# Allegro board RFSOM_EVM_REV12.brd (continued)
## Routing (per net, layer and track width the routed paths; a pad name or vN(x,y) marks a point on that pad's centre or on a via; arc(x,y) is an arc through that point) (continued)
DVDDL: length 8.6
  TOP w0.203: 377.1,63.21 U12.38
  TOP w0.305: v1(376.78,63.21) 377.1,63.21
  TOP w0.381: v1(374.49,59.45) 374.83,59.79 FB9.1 375.27,59.11 v1(374.49,58.33)
  ART10 w0.508: v1(376.78,63.21) 376.78,61.86 374.49,59.56 v1(374.49,59.45)
VBUS: length 9.4
  TOP w0.381: D2.2 v1(397.99,4.42) ; 394.61,12.7 v1(395.15,12.17) ; 394.61,12.7 v1(394.08,12.17) ; 394.61,12.7 C15.1 ; D1.2 v1(396.09,11.86) ; J4.A9 v1(398.83,9.62) ; J4.B4 v1(400.53,9.37) ; J4.B9 v1(401.98,6.87) ; U9.1 v1(393.87,-1.46) ; J4.A4 v1(398.83,6.62) ; U9.3 v1(395.77,-1.46)
  BOTTOM w0.508: v1(396.09,11.86) 396.54,12.31 C16.1
VCC_1V8_FT: length 9.5
  TOP w0.254: v1(380.08,-1.47) 380.58,-0.97 U2.49 ; U2.37 379.24,5.61 v1(378.99,5.86) ; v1(388.32,-1.47) 388.08,-1.23 U2.64 ; U2.12 v1(389.66,5.61)
  BOTTOM w0.381: v1(389.66,5.61) 388.54,6.73 C25.1
  BOTTOM w0.508: C28.1 v1(378.99,5.86) ; v1(380.08,-1.47) 379.68,-1.87 C26.1 ; C27.1 v1(388.32,-1.47)
VCC_3V3_FT: length 35
  TOP w0.254: v1(386.33,9.2) 386.58,8.95 U2.20 ; U2.42 v1(378.99,3.11) ; U2.31 v1(381.08,9.2) ; U2.56 v1(384.08,-1.47) ; U2.50 v1(381.08,-1.47)
  TOP w0.381: U4.1 v1(390.86,13.23) C3.1 ; C1.1 v1(382.48,13.23) U3.1 ; C5.1 v1(388.06,13.23) U5.1 ; U5.5 v1(388.72,17.12) ; U8.1 v1(376.89,13.23) C17.1 ; U9.5 v1(393.87,3.24) ; U10.8 v1(377.8,-5.35) ; U3.5 v1(383.13,17.12) ; U4.5 v1(391.52,17.12) ; U6.1 v1(385.27,13.23) C7.1 ; U7.5 v1(380.34,17.12) ; FB1.1 v1(391.82,-1.71) ; U7.1 v1(379.68,13.23) C12.1
  BOTTOM w0.381: C22.1 386.05,8.92 v1(386.33,9.2) 387.02,8.51 C21.1
  BOTTOM w0.508: C20.1 378.93,3.17 v1(378.99,3.11) ; C9.1 380.54,-0.43 381.08,-0.97 v1(381.08,-1.47) ; C24.1 394.41,2.7 v1(393.87,3.24) ; R20.2 v1(384.62,-2.6) ; R20.2 R19.2 384.21,-1.6 v1(384.08,-1.47) 384.07,-1.47 383.57,-0.96 C10.1 ; R20.2 R17.2 ; C19.1 v1(381.08,9.2) ; U10.8 v1(377.8,-5.35)
  vias: v1(392.75,7.76) v1(392.75,6.49)
VCC_5V: length 28.4
  TOP w0.254: v1(385.44,39.06) U15.21
  TOP w0.381: J1.C1 v1(228.1,91.77) ; U19.C1 v1(232.85,119.81) ; J1.B2 v1(229.37,90.5) ; U19.G1 v1(239.2,119.81) ; J1.E1 v1(224.29,91.77) ; J2.F1 v1(321.98,91.77) ; J1.B1 v1(229.37,91.77) ; U19.D2 v1(234.12,121.08) ; J1.E2 v1(224.29,90.5) ; J1.G1 v1(221.75,91.77) ; U19.F1 v1(236.66,119.81) ; U19.J1 v1(241.74,119.81) ; U19.D1 v1(234.12,119.81) ; J2.G2 v1(320.71,90.5) ; J1.G2 v1(221.75,90.5) ; U19.K2 v1(243.01,121.08) ; J1.F1 v1(223.02,91.77) ; U19.A2 v1(230.31,121.08) ; U17.7 v1(392.89,30.78) ; U19.G2 v1(239.2,121.08) ; J1.C2 v1(228.1,90.5) ; J2.G1 v1(320.71,91.77) ; J1.D1 v1(226.83,91.77) ; U19.A3 v1(230.31,122.35) ; U19.A1 v1(230.31,119.81) ; J1.F2 v1(223.02,90.5) ; U19.K1 v1(243.01,119.81) ; J1.D2 v1(226.83,90.5)
  BOTTOM w0.508: RP12.1 236.02,120.45 v1(236.66,119.81)
  vias: v1(221.75,92.77) v1(225.56,91.77) v1(225.56,90.77) v1(225.56,89.77) v1(226.83,92.77) v1(228.1,92.77) v1(229.37,92.77) v1(230.66,106.81) v1(230.66,105.81) v1(231.66,111.81) v1(231.66,110.81) v1(231.66,106.81) v1(231.66,105.81) v1(232.66,118.81) v1(232.66,117.81) v1(232.66,116.81) v1(232.66,115.81) v1(232.66,111.81) v1(232.66,110.81) v1(232.66,106.81) v1(232.66,105.81) v1(233.66,118.81) v1(233.66,117.81) v1(233.66,116.81) v1(233.66,115.81) v1(233.66,114.81) v1(233.66,113.81) v1(233.66,112.81) v1(233.66,111.81) v1(233.66,110.81) v1(233.66,109.81) v1(233.66,108.81) v1(233.66,107.81) v1(233.66,106.81) v1(233.66,105.81) v1(234.66,118.81) v1(234.66,117.81) v1(234.66,116.81) v1(234.66,115.81) v1(234.66,114.81) v1(234.66,113.81) v1(234.66,112.81) v1(234.66,111.81) v1(234.66,110.81) v1(234.66,109.81) v1(234.66,108.81) v1(234.66,107.81) v1(234.66,106.81) v1(234.66,105.81) v1(235.66,118.81) v1(235.66,117.81) v1(235.66,116.81) v1(235.66,115.81) v1(235.66,114.81) v1(235.66,113.81) v1(235.66,112.81) v1(235.66,111.81) v1(235.66,110.81) v1(235.66,109.81) v1(235.66,108.81) v1(235.66,107.81) v1(235.66,106.81) v1(235.66,105.81) v1(236.66,118.81) v1(236.66,117.81) v1(236.66,116.81) v1(236.66,115.81) v1(236.66,114.81) v1(236.66,113.81) v1(236.66,112.81) v1(236.66,111.81) v1(236.66,110.81) v1(236.66,109.81) v1(236.66,108.81) v1(236.66,107.81) v1(236.66,106.81) v1(236.66,105.81) v1(237.66,118.81) v1(237.66,117.81) v1(237.66,116.81) v1(237.66,115.81) v1(237.66,114.81) v1(237.66,113.81) v1(237.66,112.81) v1(237.66,111.81) v1(237.66,110.81) v1(237.66,109.81) v1(237.66,108.81) v1(237.66,107.81) v1(237.66,106.81) v1(237.66,105.81) v1(238.66,118.81) v1(238.66,117.81) v1(238.66,116.81) v1(238.66,115.81) v1(238.66,114.81) v1(238.66,113.81) v1(238.66,112.81) v1(238.66,111.81) v1(238.66,110.81) v1(238.66,109.81) v1(238.66,108.81) v1(238.66,107.81) v1(238.66,106.81) v1(238.66,105.81) v1(239.66,118.81) v1(239.66,117.81) v1(239.66,116.81) v1(239.66,115.81) v1(239.66,114.81) v1(239.66,113.81) v1(239.66,112.81) v1(239.66,111.81) v1(239.66,110.81) v1(239.66,109.81) v1(239.66,108.81) v1(239.66,107.81) v1(239.66,106.81) v1(239.66,105.81) v1(240.66,118.81) v1(240.66,117.81) v1(240.66,116.81) v1(240.66,115.81) v1(240.66,114.81) v1(240.66,113.81) v1(240.66,112.81) v1(240.66,111.81) v1(240.66,110.81) v1(240.66,109.81) v1(240.72,108.83) v1(240.66,107.81) v1(240.66,106.81) v1(240.66,105.81) v1(241.66,118.81) v1(241.66,117.81) v1(241.66,116.81) v1(241.66,115.81) v1(241.66,111.81) v1(241.66,110.81) v1(241.66,106.81) v1(241.66,105.81) v1(242.66,118.81) v1(242.66,117.81) v1(242.66,116.81) v1(242.66,115.81) v1(242.66,111.81) v1(242.66,110.81) v1(242.66,106.81) v1(242.66,105.81) v1(243.66,117.81) v1(243.66,116.81) v1(243.66,115.81) v1(243.66,111.81) v1(243.66,110.81) v1(243.66,106.81) v1(243.66,105.81)
VCC_12V: length 15.2
  TOP w0.381: U19.L4 v1(244.28,124.89) ; 299.61,118.16 299.05,118.16 v1(298.09,117.21) ; U19.H5 v1(240.47,126.16) ; U19.B3 v1(231.58,122.35) ; U19.L5 v1(244.28,126.16) ; U19.E3 v1(235.39,122.35) ; U19.B5 v1(231.58,126.16) ; U19.E5 v1(235.39,126.16) ; U19.B4 v1(231.58,124.89) ; U19.E4 v1(235.39,124.89) ; U19.H3 v1(240.47,122.35) ; U19.L3 v1(244.28,122.35) ; U19.H4 v1(240.47,124.89)
  BOTTOM w0.508: RP3.1 231.91,126.49 v1(231.58,126.16) ; v1(240.47,126.16) 240.5,126.16 RP5.1 ; RP6.1 v1(242.13,131.8) ; v1(235.39,126.16) 235.72,126.49 RP4.1
  vias: v1(225.23,131.24) v1(225.23,129.97) v1(225.23,128.7) v1(225.23,127.43) v1(225.23,126.16) v1(225.23,124.89) v1(225.23,123.62) v1(225.23,122.35) v1(225.23,121.08) v1(225.23,119.81) v1(225.23,118.54) v1(226.5,131.24) v1(226.5,129.97) v1(226.5,128.7) v1(226.5,127.43) v1(226.5,126.16) v1(226.5,124.89) v1(226.5,123.62) v1(226.5,122.35) v1(226.5,121.08) v1(226.5,119.81) v1(226.5,118.54) v1(227.77,131.24) v1(227.77,129.97) v1(227.77,128.7) v1(227.77,127.43) v1(227.77,126.16) v1(227.77,124.89) v1(227.77,123.62) v1(227.77,122.35) v1(227.77,121.08) v1(227.77,119.81) v1(227.77,118.54) v1(245.17,126.85) v1(245.17,125.58) v1(245.17,124.31) v1(245.17,123.04) v1(245.17,121.77) v1(245.17,120.5) v1(246.44,126.85) v1(246.44,125.58) v1(246.44,124.31) v1(246.44,123.04) v1(246.44,121.77) v1(246.44,120.5) v1(290.47,117.21) v1(290.47,115.94) v1(290.47,114.67) v1(291.74,117.21) v1(291.74,115.94) v1(291.74,114.67) v1(293.01,117.21) v1(293.01,115.94) v1(293.01,114.67) v1(294.28,117.21) v1(294.28,115.94) v1(294.28,114.67) v1(295.55,117.21) v1(295.55,115.94) v1(295.55,114.67) v1(296.82,117.21) v1(296.82,115.94) v1(296.82,114.67) v1(298.09,115.94) v1(298.09,114.67) v1(299.36,117.21) v1(299.36,115.94) v1(299.36,114.67) v1(300.63,117.21) v1(300.63,115.94) v1(300.63,114.67) v1(301.9,117.21) v1(301.9,115.94) v1(301.9,114.67) v1(303.17,117.21) v1(303.17,115.94) v1(303.17,114.67) v1(304.44,117.21) v1(304.44,115.94) v1(304.44,114.67) v1(359.54,39.12) v1(359.54,37.85) v1(359.54,36.58) v1(359.54,34.04) v1(359.54,32.77) v1(359.54,31.5) v1(359.54,30.23) v1(359.54,28.96) v1(359.54,27.69) v1(359.54,26.42) v1(359.54,25.15) v1(359.54,23.88) v1(359.54,22.61) v1(359.54,21.34) v1(359.54,20.07) v1(359.54,18.8) v1(359.54,17.53) v1(359.54,14.99) v1(359.54,13.72) v1(359.54,12.45) v1(359.54,11.18) v1(359.54,9.91) v1(359.54,8.64) v1(359.54,7.37) v1(360.81,39.12) v1(360.81,37.85) v1(360.81,36.58) v1(360.81,34.04) v1(360.81,32.77) v1(360.81,31.5) v1(360.81,30.23) v1(360.81,28.96) v1(360.81,27.69) v1(360.81,26.42) v1(360.81,25.15) v1(360.81,23.88) v1(360.81,22.61) v1(360.81,21.34) v1(360.81,20.07) v1(360.81,18.8) v1(360.81,17.53) v1(360.81,14.99) v1(360.81,13.72) v1(360.81,12.45) v1(360.81,11.18) v1(360.81,9.91) v1(360.81,8.64) v1(360.81,7.37)
VCCO_89: length 2.7
  TOP w0.381: J2.B2 v1(328.33,90.5) ; J2.C2 v1(327.06,90.5) ; J2.C1 v1(327.06,91.77)
  vias: v1(322.63,107.16) v1(322.63,105.89) v1(322.63,104.62) v1(323.9,107.16) v1(323.9,105.89) v1(323.9,104.62) v1(325.17,107.16) v1(325.17,105.89) v1(325.17,104.62) v1(326.44,107.16) v1(326.44,105.89) v1(326.44,104.62)
VCCO_501: length 2.7
  TOP w0.381: J2.F2 v1(321.98,90.5) ; J2.E1 v1(323.25,91.77) ; J2.E2 v1(323.25,90.5)
  vias: v1(313.28,107.16) v1(313.28,105.89) v1(313.28,104.62) v1(314.55,107.16) v1(314.55,105.89) v1(314.55,104.62) v1(315.82,107.16) v1(315.82,105.89) v1(315.82,104.62) v1(317.09,107.16) v1(317.09,105.89) v1(317.09,104.62)
VCCO_502: length 2.7
  TOP w0.381: J2.D1 v1(325.79,91.77) ; J2.B1 v1(328.33,91.77) ; J2.D2 v1(325.79,90.5)
  vias: v1(317.96,107.16) v1(317.96,105.89) v1(317.96,104.62) v1(319.23,107.16) v1(319.23,105.89) v1(319.23,104.62) v1(320.5,107.16) v1(320.5,105.89) v1(320.5,104.62) v1(321.77,107.16) v1(321.77,105.89) v1(321.77,104.62)
VDD33: length 1.4
  TOP w0.203: v1(379.22,60.48) 379.22,60.86 379.44,61.08 U12.3
VDDH: length 9.3
  TOP w0.203: U12.8 381.44,59.27 v1(382.37,58.33) ; U12.27 v1(379.84,67.46)
  TOP w0.381: RL10.2 374.57,62.24 v1(374.34,62.01) ; RL15.2 v1(382.2,71.04) ; RL14.2 v1(381.2,71.04) ; RL21.2 v1(376.2,71.04) ; RL11.2 v1(384.2,71.04)
  BOTTOM w0.254: CL18.2 v1(382.37,58.33)
  BOTTOM w0.508: CL17.2 379.69,67.32 v1(379.84,67.46)
BANK128_MGT_CLK1_N: length 33.6
  TOP w0.114: v1(337.76,24.04) 337.59,24.2 arc(337.48,24.37) 337.44,24.57 337.44,24.69 arc(337.49,24.8) 337.6,24.85 340.79,24.85 arc(341.05,24.8) 341.27,24.65 341.29,24.63 arc(341.51,24.48) 341.77,24.43 XS1.5
  TOP w0.173: J2.E40 v1(324.52,42.24)
  ART05 w0.102: v1(337.76,24.04) 337.49,24.3 arc(337.46,24.36) 337.44,24.42 337.44,25.63 arc(337.29,26.4) 336.86,27.04 335.79,28.12 arc(335.39,28.71) 335.25,29.41 335.25,35.5 arc(333.42,39.92) 329,41.75 324.62,41.75 arc(324.55,41.78) 324.52,41.85 v1(324.52,42.24)
BANK128_MGT_CLK1_P: length 33.5
  TOP w0.114: XS1.4 341.77,25.53 arc(341.51,25.48) 341.29,25.34 341.27,25.32 arc(341.05,25.17) 340.79,25.12 337.6,25.12 arc(337.3,24.99) 337.17,24.69 337.17,24.59 arc(337.13,24.38) 337.02,24.21 v1(336.84,24.04)
  TOP w0.173: J2.D40 v1(324.52,40.97)
  ART05 w0.102: v1(324.52,40.97) 324.52,41.36 arc(324.55,41.43) 324.62,41.46 329,41.46 arc(333.22,39.72) 334.96,35.5 334.96,29.41 arc(335.12,28.6) 335.58,27.91 336.66,26.84 arc(337.03,26.29) 337.16,25.63 337.16,24.39 arc(337.15,24.35) 337.13,24.32 v1(336.84,24.04)
BANK128_MGT_RX0_N: length 75.7
  TOP w0.114: J12.18 359.12,91.53 arc(359.28,91.5) 359.42,91.4 359.44,91.39 arc(359.58,91.29) 359.74,91.26 359.79,91.26 arc(359.98,91.3) 360.14,91.41 v1(360.32,91.59)
  TOP w0.173: J2.C39 v1(327.06,42.24)
  ART10 w0.102: v1(327.06,42.24) 327.49,42.67 arc(327.59,42.74) 327.71,42.76 328.66,42.76 330.16,42.49 332.73,42.95 336.09,42.35 338.11,42.71 339.83,43.91 341.79,44.26 344.15,45.91 346.07,48.65 347.85,49.89 348.93,51.44 350.28,52.39 351.35,53.91 351.64,55.56 353.48,58.18 356.39,60.22 359.09,64.08 359.92,68.78 359.41,71.7 360.04,75.28 361.47,77.33 361.84,79.42 361.65,80.47 361.79,81.25 362.66,82.49 363,84.44 363,90.15 arc(362.68,90.93) 361.91,91.25 360.75,91.25 arc(360.67,91.26) 360.59,91.31 v1(360.32,91.59)
BANK128_MGT_RX0_P: length 75.7
  TOP w0.114: J12.17 359.12,90.73 arc(359.28,90.76) 359.42,90.85 359.44,90.87 arc(359.58,90.96) 359.74,90.99 359.79,90.99 arc(359.98,90.96) 360.14,90.85 v1(360.32,90.67)
  TOP w0.173: J2.B39 v1(327.06,43.51)
  ART10 w0.102: v1(360.32,90.67) 360.59,90.94 arc(360.67,90.99) 360.75,91.01 361.91,91.01 arc(362.52,90.76) 362.77,90.15 362.77,89.85 362.55,89.63 362.55,89.44 362.77,89.23 362.77,89.04 362.55,88.82 362.55,88.63 362.77,88.41 362.77,88.22 362.55,88.01 362.55,87.82 362.77,87.6 362.77,87.41 362.55,87.19 362.55,87 362.77,86.79 362.77,84.46 362.44,82.58 361.57,81.34 361.41,80.47 361.6,79.42 361.25,77.42 359.81,75.38 359.17,71.7 359.68,68.78 358.87,64.17 356.22,60.39 353.31,58.35 351.42,55.65 351.13,54 350.11,52.56 348.76,51.61 347.68,50.06 345.9,48.82 343.98,46.08 341.7,44.48 339.74,44.14 338.02,42.93 336.09,42.59 332.73,43.19 330.16,42.73 328.68,43 327.71,43 arc(327.59,43.02) 327.49,43.08 v1(327.06,43.51)
BANK128_MGT_RX1_N: length 69.3
  TOP w0.114: J12.21 355.35,91.13 arc(355.22,91.1) 355.11,91.03 355.04,90.96 arc(354.93,90.89) 354.81,90.86 354.79,90.86 arc(354.66,90.89) 354.56,90.96 v1(354.33,91.18)
  TOP w0.173: J2.G37 v1(321.98,46.05)
  ART10 w0.102: v1(321.98,46.05) 322.41,45.62 arc(322.51,45.56) 322.63,45.54 326.03,45.54 arc(326.18,45.59) 326.24,45.74 326.24,46.38 arc(326.36,46.67) 326.64,46.79 328.02,46.79 328.65,46.9 328.75,46.9 328.75,46.9 329.68,46.9 330.3,46.79 331.83,47.06 332.77,47.72 334.98,48.11 336.12,48.9 337.73,49.19 338.97,50.06 339.82,51.26 341.21,52.24 342.9,54.66 343.13,55.93 344.17,57.41 345.16,63.02 344.91,64.44 345.27,66.48 344.8,69.14 345.23,71.57 344.77,74.14 345.04,75.64 344.85,76.74 344.85,76.75 344.84,76.76 345.9,82.73 350.78,89.7 352.07,90.61 353.42,90.85 353.9,90.85 arc(353.98,90.86) 354.06,90.91 v1(354.33,91.18)
BANK128_MGT_RX1_P: length 69.3
  TOP w0.114: J12.22 355.35,90.33 arc(355.22,90.35) 355.11,90.43 355.04,90.5 arc(354.94,90.57) 354.81,90.59 354.79,90.59 arc(354.66,90.57) 354.56,90.5 v1(354.33,90.27)
  TOP w0.173: J2.F37 v1(321.98,44.78)
  ART10 w0.102: v1(321.98,44.78) 322.41,45.21 arc(322.51,45.28) 322.63,45.3 326.03,45.3 arc(326.35,45.43) 326.47,45.74 326.47,46.38 arc(326.52,46.5) 326.64,46.55 328.04,46.55 328.65,46.66 328.75,46.66 328.75,46.66 329.66,46.66 330.3,46.55 331.92,46.83 332.87,47.49 335.08,47.88 336.21,48.68 337.82,48.96 339.14,49.89 339.99,51.09 341.38,52.07 343.13,54.57 343.35,55.84 344.39,57.32 345.4,63.02 345.15,64.44 345.51,66.48 345.04,69.14 345.47,71.57 345.01,74.14 345.28,75.64 345.08,76.76 346.12,82.64 350.95,89.53 352.16,90.38 353.44,90.61 353.9,90.61 arc(353.98,90.59) 354.06,90.54 v1(354.33,90.27)
BANK128_MGT_RX2_N: length 71.8
  TOP w0.114: J12.15 359.12,89.13 arc(359.28,89.1) 359.42,89 359.44,88.99 arc(359.58,88.89) 359.74,88.86 359.79,88.86 arc(359.98,88.9) 360.14,89.01 v1(360.32,89.19)
  TOP w0.173: v1(324.52,44.78) J2.E38
  ART10 w0.102: v1(324.52,44.78) 324.95,44.35 arc(325.05,44.29) 325.17,44.27 328.25,44.27 329.46,44.48 330.34,44.32 331.5,44.53 332.87,44.29 334.25,44.53 334.95,45.02 336.36,45.27 337.73,46.23 339.1,46.47 340.13,47.19 341.79,47.49 343.21,48.48 345.12,51.2 345.32,52.34 346.22,53.62 346.53,55.37 348.54,58.25 349.81,65.44 349.14,69.23 349.65,72.1 349.21,74.62 350.47,81.8 351.06,82.63 352.78,83.84 354.49,84.14 355.19,84.63 355.89,85.63 356.28,87.81 356.53,88.17 357.28,88.7 358.11,88.85 359.74,88.85 arc(359.96,88.89) 360.15,89.02 v1(360.32,89.19)
BANK128_MGT_RX2_P: length 71.8
  TOP w0.114: v1(360.32,88.27) 360.14,88.45 arc(359.98,88.56) 359.79,88.59 359.74,88.59 arc(359.58,88.56) 359.44,88.47 359.42,88.45 arc(359.28,88.36) 359.12,88.33 J12.14
  TOP w0.173: v1(324.52,43.51) J2.D38
  ART10 w0.102: v1(360.32,88.27) 360.15,88.44 arc(359.96,88.56) 359.74,88.61 359.17,88.61 arc(359.17,88.61) 359.16,88.61 358.14,88.61 357.38,88.48 356.7,88 356.5,87.72 356.12,85.54 355.36,84.46 354.59,83.92 352.87,83.62 351.22,82.46 350.7,81.71 349.45,74.62 349.89,72.1 349.38,69.23 350.05,65.44 348.77,58.16 346.75,55.28 346.44,53.53 345.54,52.25 345.34,51.11 343.38,48.31 341.89,47.26 340.22,46.97 339.19,46.25 337.83,46.01 336.45,45.04 335.04,44.8 334.34,44.31 332.87,44.05 331.5,44.29 330.34,44.08 329.46,44.24 328.27,44.03 325.17,44.03 arc(325.05,44.01) 324.95,43.94 v1(324.52,43.51)
BANK128_MGT_RX3_N: length 63.2
  TOP w0.114: J12.24 355.35,88.73 arc(355.22,88.7) 355.11,88.63 355.04,88.56 arc(354.93,88.49) 354.81,88.46 354.79,88.46 arc(354.66,88.49) 354.56,88.56 v1(354.33,88.78)
  TOP w0.173: J2.C37 v1(327.06,46.05)
  ART10 w0.102: v1(354.33,88.78) 354.06,88.52 arc(353.98,88.46) 353.89,88.45 353.43,88.45 352.59,88.3 351.85,87.78 351.46,87.23 351.29,86.23 348.37,82.06 347.7,78.28 347.95,76.86 347.23,72.78 347.45,71.55 347.06,69.35 347.24,68.35 347.56,66.5 347.23,64.63 347.6,62.5 347.27,60.59 346.35,59.28 345.98,57.15 345.03,55.8 344.77,54.28 343.82,52.93 343.51,51.16 342.61,49.88 341.01,48.76 339.89,48.56 338.68,47.71 337.43,47.49 336.27,46.67 334.75,46.41 333.67,45.65 332.21,45.39 331.07,45.59 329.92,45.39 329.09,45.54 327.71,45.54 arc(327.59,45.56) 327.49,45.62 v1(327.06,46.05)
BANK128_MGT_RX3_P: length 63.2
  TOP w0.114: J12.25 355.36,87.93 355.35,87.93 arc(355.22,87.95) 355.11,88.03 355.04,88.1 arc(354.94,88.17) 354.81,88.19 354.79,88.19 arc(354.66,88.17) 354.56,88.1 v1(354.33,87.87)
  TOP w0.173: J2.B37 v1(327.06,44.78)
  ART10 w0.102: v1(327.06,44.78) 327.49,45.21 arc(327.59,45.28) 327.71,45.3 329.07,45.3 329.92,45.15 331.07,45.35 332.21,45.15 333.76,45.43 334.84,46.18 336.36,46.45 337.52,47.26 338.77,47.48 339.99,48.34 341.1,48.53 342.78,49.71 343.73,51.06 344.04,52.84 344.99,54.19 345.26,55.71 346.2,57.06 346.58,59.19 347.49,60.5 347.84,62.5 347.47,64.63 347.8,66.5 347.47,68.39 347.3,69.35 347.69,71.55 347.47,72.78 348.19,76.86 347.94,78.28 348.59,81.97 351.51,86.14 351.69,87.14 352.02,87.61 352.68,88.07 353.45,88.21 353.89,88.21 arc(353.98,88.19) 354.06,88.14 v1(354.33,87.87)
BANK128_MGT_TX0_N: length 65.8
  TOP w0.114: J12.37 355.35,78.33 arc(355.22,78.35) 355.11,78.43 355.04,78.5 arc(354.94,78.57) 354.81,78.59 354.79,78.59 arc(354.66,78.57) 354.56,78.5 354.33,78.27
  TOP w0.173: J2.G41 321.98,39.7
  ART03 w0.102: 354.33,78.27 354.04,78.56 arc(353.98,78.6) 353.92,78.61 352.78,78.61 350.05,78.13 350.01,78.12 349.26,77.99 347,76.41 345.75,74.62 344.91,69.82 345.95,63.93 345.44,61.09 345.82,58.96 344.91,53.78 343.51,51.78 342.97,48.71 341.09,46.02 338.72,44.37 334.82,43.68 330.75,44.4 328.71,44.04 325.85,44.04 arc(325.7,44.01) 325.58,43.93 325.49,43.84 325.48,43.83 arc(325.4,43.71) 325.37,43.57 325.37,43.39 arc(325.33,43.18) 325.22,43.01 325.15,42.94 arc(324.94,42.81) 324.7,42.76 324.29,42.76 arc(324.17,42.74) 324.08,42.67 324.02,42.61 arc(323.94,42.5) 323.92,42.36 323.92,40.89 arc(323.88,40.7) 323.77,40.54 323.62,40.39 arc(323.43,40.26) 323.22,40.22 322.79,40.22 arc(322.52,40.17) 322.3,40.02 321.98,39.7
BANK128_MGT_TX0_P: length 65.8
  TOP w0.114: J12.36 355.35,79.13 arc(355.22,79.1) 355.11,79.03 355.04,78.96 arc(354.93,78.89) 354.81,78.86 354.79,78.86 arc(354.66,78.89) 354.56,78.96 354.33,79.18
  TOP w0.173: J2.F41 321.98,40.97
  ART03 w0.102: 354.33,79.18 354.04,78.9 arc(353.98,78.86) 353.92,78.85 352.76,78.85 350.01,78.36 349.17,78.21 346.83,76.58 345.53,74.71 344.67,69.82 345.71,63.93 345.2,61.09 345.58,58.96 344.68,53.87 343.28,51.87 342.74,48.8 340.92,46.19 338.63,44.59 334.82,43.92 330.75,44.64 328.68,44.28 325.85,44.28 arc(325.61,44.23) 325.41,44.09 325.31,44 arc(325.18,43.8) 325.14,43.57 325.14,43.39 arc(325.11,43.27) 325.05,43.18 324.98,43.11 arc(324.85,43.02) 324.7,42.99 324.29,42.99 arc(324.08,42.95) 323.91,42.84 323.85,42.78 arc(323.72,42.59) 323.68,42.36 323.68,40.89 arc(323.66,40.79) 323.6,40.7 323.45,40.55 arc(323.34,40.48) 323.22,40.46 322.73,40.46 arc(322.52,40.5) 322.34,40.62 321.98,40.97
BANK128_MGT_TX1_N: length 73.9
  TOP w0.114: 360.32,78.67 360.15,78.84 arc(359.98,78.95) 359.78,78.99 359.69,78.99 arc(359.53,78.96) 359.39,78.87 359.37,78.85 arc(359.23,78.76) 359.07,78.73 J12.2
  TOP w0.173: J2.E42 324.52,39.7
  ART03 w0.102: 324.52,39.7 324.84,39.39 arc(325.06,39.24) 325.33,39.19 325.77,39.19 arc(325.92,39.22) 326.05,39.3 326.13,39.38 arc(326.18,39.46) 326.2,39.56 326.2,41.12 arc(326.24,41.31) 326.35,41.47 326.41,41.54 arc(326.61,41.67) 326.84,41.71 329.16,41.71 331.56,41.29 332.83,41.51 334.21,41.27 338.96,42.11 343.5,45.29 346.07,48.96 346.64,52.18 347.76,53.77 348.26,56.62 347.54,60.68 348.3,64.97 347.39,70.13 347.86,72.83 349.17,74.7 349.73,75.09 350.06,75.33 352.15,75.7 353.6,75.45 355.62,75.81 355.63,75.8 357.17,75.8 357.46,76.09 357.78,76.09 358.07,75.8 358.39,75.8 358.68,76.09 359,76.09 359.29,75.8 359.61,75.8 359.9,76.09 360.22,76.09 360.51,75.8 360.82,75.8 arc(361.32,76.01) 361.53,76.52 361.53,78.43 arc(361.49,78.67) 361.36,78.86 arc(361.19,78.97) 361,79.01 360.73,79.01 arc(360.66,79) 360.61,78.96 360.32,78.67
BANK128_MGT_TX1_P: length 73.9
  TOP w0.114: 360.32,79.59 360.14,79.41 arc(359.98,79.3) 359.79,79.26 359.74,79.26 arc(359.58,79.29) 359.44,79.39 359.42,79.4 arc(359.28,79.5) 359.12,79.53 J12.3
  TOP w0.173: J2.D42 324.52,38.43
  ART03 w0.102: 360.32,79.59 360.61,79.3 arc(360.66,79.26) 360.73,79.25 361,79.25 arc(361.28,79.19) 361.53,79.03 arc(361.71,78.76) 361.77,78.43 361.77,76.52 arc(361.49,75.85) 360.82,75.57 355.63,75.57 353.6,75.21 352.15,75.46 350.16,75.11 349.87,74.9 349.34,74.53 348.09,72.73 347.63,70.13 348.54,64.97 347.78,60.68 348.5,56.62 347.98,53.68 346.86,52.08 346.29,48.87 343.67,45.12 341.37,43.5 339.05,41.88 334.21,41.03 332.83,41.27 331.56,41.05 329.14,41.48 326.84,41.48 arc(326.7,41.45) 326.58,41.37 326.51,41.3 arc(326.46,41.22) 326.44,41.12 326.44,39.56 arc(326.4,39.37) 326.29,39.21 326.21,39.13 arc(326.01,39) 325.77,38.95 325.33,38.95 arc(325.06,38.9) 324.84,38.75 324.83,38.74 324.52,38.43
BANK128_MGT_TX2_N: length 66.4
  TOP w0.114: 354.33,80.67 354.56,80.9 arc(354.66,80.97) 354.79,80.99 354.81,80.99 arc(354.94,80.97) 355.04,80.9 355.09,80.85 arc(355.23,80.76) 355.39,80.73 J12.34
  TOP w0.173: J2.G39 321.98,42.24
  ART03 w0.102: 354.33,80.67 354.04,80.96 arc(353.98,81) 353.92,81.01 352.87,81.01 351.46,80.76 350.65,80.9 348.88,80.59 345.76,78.41 343.13,74.65 342.46,70.88 343.76,63.53 343.34,61.14 343.74,58.85 343.05,54.9 340.86,51.78 340.49,49.67 339.23,47.88 337.65,46.77 333.93,46.11 330.94,46.64 326.89,46.64 arc(326.58,46.51) 326.45,46.2 326.45,45.96 arc(326.25,45.48) 325.77,45.28 323.12,45.28 arc(322.92,45.2) 322.83,45 322.83,43.14 arc(322.72,42.87) 322.46,42.76 322.08,42.76 arc(322.01,42.73) 321.98,42.66 321.98,42.24
BANK128_MGT_TX2_P: length 66.4
  TOP w0.114: 354.33,81.58 354.56,81.36 arc(354.66,81.29) 354.79,81.26 354.81,81.26 arc(354.93,81.29) 355.04,81.36 355.09,81.4 arc(355.23,81.5) 355.39,81.53 J12.33
  TOP w0.173: J2.F39 321.98,43.51
  ART03 w0.102: 321.98,43.51 321.98,43.1 arc(322.01,43.03) 322.08,43 322.46,43 arc(322.56,43.04) 322.6,43.14 322.6,45 arc(322.75,45.36) 323.12,45.52 325.77,45.52 arc(326.08,45.65) 326.21,45.96 326.21,46.2 arc(326.41,46.68) 326.89,46.88 330.96,46.88 333.93,46.35 337.55,46.99 339.06,48.05 340.26,49.76 340.63,51.87 342.82,54.99 343.5,58.85 343.1,61.14 343.52,63.53 342.22,70.88 342.91,74.74 345.59,78.58 348.78,80.82 350.65,81.14 351.46,81 352.85,81.25 353.92,81.25 arc(353.98,81.26) 354.04,81.3 354.33,81.58
BANK128_MGT_TX3_N: length 75.8
  TOP w0.114: J12.5 359.07,81.13 arc(359.23,81.16) 359.37,81.25 359.39,81.27 arc(359.53,81.36) 359.69,81.39 359.78,81.39 arc(359.98,81.35) 360.15,81.24 360.32,81.07
  TOP w0.173: J2.C41 327.06,40.97
  ART03 w0.102: 327.06,40.97 327.33,40.71 arc(327.61,40.52) 327.94,40.46 328.68,40.46 329.79,40.26 330.67,39.64 332.46,39.33 334.2,39.64 336.64,39.21 339.01,39.62 341.41,41.3 344.31,41.81 345.92,42.94 347.09,44.61 347.47,46.76 348.68,48.5 349.15,51.16 350.49,53.06 351.01,56.04 350.21,60.59 350.75,63.65 351.41,64.6 352.05,65.04 353.27,65.26 354.82,64.99 356.58,65.3 357.67,66.85 358.53,67.45 359.75,68.28 360.16,68.86 362.36,70.4 363.15,71.53 363.97,72.35 arc(364.21,72.71) 364.3,73.13 364.3,75.68 364,75.97 364,76.29 364.3,76.58 364.3,76.9 364,77.19 364,77.51 364.3,77.8 364.3,78.12 364,78.41 364,78.73 364.3,79.02 364.3,80.66 arc(364.08,81.19) 363.55,81.41 360.73,81.41 arc(360.66,81.4) 360.61,81.36 360.32,81.07
BANK128_MGT_TX3_P: length 75.8
  TOP w0.114: 360.32,81.99 360.14,81.81 arc(359.98,81.7) 359.79,81.66 359.74,81.66 arc(359.58,81.69) 359.44,81.79 359.42,81.8 arc(359.28,81.9) 359.12,81.93 J12.6
  TOP w0.173: J2.B41 327.06,39.7
  ART03 w0.102: 360.32,81.99 360.61,81.7 arc(360.66,81.66) 360.73,81.65 363.55,81.65 arc(364.24,81.36) 364.53,80.66 364.53,73.13 arc(364.43,72.62) 364.14,72.19 363.34,71.38 362.53,70.23 360.33,68.69 359.92,68.11 358.57,67.17 358.53,67.16 357.84,66.68 356.72,65.08 354.82,64.75 353.27,65.02 352.14,64.82 351.58,64.43 350.97,63.56 350.45,60.59 351.25,56.04 350.71,52.97 349.38,51.07 348.91,48.41 347.69,46.67 347.31,44.51 346.09,42.77 344.4,41.59 341.5,41.08 339.11,39.4 336.64,38.97 334.2,39.4 332.46,39.09 330.57,39.42 329.69,40.04 328.66,40.22 327.94,40.22 arc(327.61,40.15) 327.33,39.97 327.06,39.7
BANK129_MGT_RX0_N: length 109.6
  TOP w0.114: v1(365.52,132.13) 365.75,131.9 arc(365.85,131.83) 365.98,131.81 366,131.81 arc(366.12,131.83) 366.23,131.9 366.28,131.95 arc(366.41,132.04) 366.58,132.07 J40.12
  TOP w0.173: J2.C31 v1(327.06,53.67)
  ART10 w0.102: v1(365.52,132.13) 365.52,131.89 arc(365.49,131.82) 365.42,131.79 364.08,131.79 361.93,132.17 360.26,131.88 358.81,130.86 354.83,130.16 350.45,127.09 348.82,124.76 344.52,121.75 341.95,118.08 341.13,113.44 342.04,108.31 340.68,100.6 341.5,95.91 340.73,91.55 341.7,86.1 341.1,82.73 341.02,82.25 341.64,78.71 341.25,76.5 341.48,75.23 341.26,73.99 341.73,71.3 341.36,69.2 341.9,66.13 341.6,64.44 341.99,62.26 341.57,59.87 340.59,58.47 340.47,57.79 337.92,54.15 336.85,53.4 334.62,53.01 333.45,53.22 330.88,52.76 328.65,53.16 327.71,53.16 arc(327.59,53.18) 327.49,53.24 v1(327.06,53.67)
BANK129_MGT_RX0_P: length 109.6
  TOP w0.114: v1(365.52,131.22) 365.75,131.45 arc(365.85,131.52) 365.98,131.54 366,131.54 arc(366.13,131.52) 366.23,131.45 366.28,131.4 arc(366.42,131.31) 366.58,131.27 J40.13
  TOP w0.173: J2.B31 v1(327.06,52.4)
  ART10 w0.102: v1(365.52,131.22) 365.52,131.45 arc(365.49,131.53) 365.42,131.56 364.06,131.56 361.93,131.93 360.35,131.65 358.9,130.64 354.93,129.94 350.62,126.92 348.99,124.6 344.69,121.58 342.17,117.99 341.37,113.44 342.28,108.31 340.92,100.6 341.74,95.91 340.97,91.55 341.94,86.1 341.34,82.73 341.26,82.25 341.88,78.71 341.49,76.5 341.72,75.23 341.5,73.99 341.97,71.3 341.6,69.2 342.14,66.13 341.84,64.44 342.23,62.26 341.79,59.78 340.81,58.38 340.69,57.7 338.09,53.98 336.94,53.18 334.62,52.77 333.45,52.98 330.88,52.52 328.63,52.92 327.71,52.92 arc(327.59,52.9) 327.49,52.83 v1(327.06,52.4)
BANK129_MGT_TX0_N: length 111.7
  TOP w0.114: 365.52,126.42 365.75,126.65 arc(365.85,126.72) 365.98,126.74 366,126.74 arc(366.13,126.72) 366.23,126.65 366.28,126.6 arc(366.42,126.51) 366.58,126.47 J40.19
  TOP w0.173: J2.E34 324.52,48.59
  ART03 w0.102: 365.52,126.42 365.52,126.65 arc(365.49,126.73) 365.42,126.76 364.69,126.76 364.15,126.66 361.22,124.61 359.65,124.34 357.13,123.89 354.59,124.34 351.47,123.79 349.16,124.2 346.66,123.75 343.73,121.7 339.69,120.99 336.39,118.68 334.79,116.39 333.9,111.35 334.16,109.86 333.17,104.23 333.9,100.07 332.25,90.69 332.81,87.5 332.1,83.45 332.82,79.39 331.76,73.38 332.29,70.35 331.87,67.93 332.24,65.82 331.26,60.27 332.18,55.07 331.57,51.62 330.4,49.94 329.57,49.37 328.1,49.11 324.62,49.11 arc(324.55,49.08) 324.52,49.01 324.52,48.59
BANK129_MGT_TX0_P: length 111.7
  TOP w0.114: 365.52,127.33 365.75,127.1 arc(365.85,127.03) 365.98,127.01 366,127.01 arc(366.12,127.03) 366.23,127.1 366.28,127.15 arc(366.41,127.24) 366.58,127.27 J40.18
  TOP w0.173: J2.D34 324.52,49.86
  ART03 w0.102: 365.52,127.33 365.52,127.09 arc(365.49,127.02) 365.42,126.99 364.67,126.99 364.05,126.88 361.13,124.84 359.65,124.58 357.13,124.13 354.59,124.58 351.47,124.03 349.16,124.44 346.57,123.98 343.64,121.92 339.6,121.21 336.22,118.85 334.56,116.48 333.66,111.35 333.92,109.86 332.93,104.23 333.66,100.07 332.01,90.69 332.57,87.5 331.87,83.49 331.86,83.45 332.58,79.39 331.53,73.42 331.52,73.38 332.05,70.35 331.63,67.93 332,65.82 331.02,60.27 331.94,55.07 331.34,51.71 330.23,50.11 329.48,49.59 329.48,49.59 328.08,49.35 324.62,49.35 arc(324.55,49.38) 324.52,49.45 324.52,49.86
BANK501_PS_MIO30: length 151.8
  TOP w0.173: J2.D8 v1(325.79,82.88)
  ART10 w0.135: J10.2 235.24,136.45 238.81,136.45 254.18,121.08 258.91,121.08 272.64,107.36 272.64,85.2 284.53,73.3 328.57,73.3 329.16,73.89 329.16,80.16 326.44,82.88 v1(325.79,82.88)
BANK501_PS_MIO31: length 136.5
  TOP w0.173: J2.C15 v1(327.06,73.99)
  ART10 w0.135: J10.3 236,137.69 238.81,137.69 254.16,122.34 259.32,122.34 273.8,107.87 273.8,85.57 284.85,74.52 326.54,74.52 v1(327.06,73.99)
BANK501_PS_MIO32: length 139.8
  TOP w0.173: J2.D10 v1(325.79,80.34)
  ART10 w0.135: v1(325.79,80.34) 326.46,80.34 327.56,79.25 327.56,77.35 327.32,77.11 285.66,77.11 276.67,86.1 276.67,108.8 259.28,126.18 254.29,126.18 240.82,139.65 238.66,139.65 237.37,140.93 237.37,142.2 237.24,142.34 235.4,142.34 J10.4
BANK501_PS_MIO33: length 135.1
  TOP w0.173: J2.B15 v1(328.33,73.99)
  ART10 w0.135: v1(328.33,73.99) 326.41,75.92 284.77,75.92 275.2,85.49 275.2,108.51 258.91,124.8 253.59,124.8 239.55,138.84 237.44,138.84 236.37,139.9 J10.5
BANK501_PS_MIO34: length 123.5
  TOP w0.173: J2.G7 v1(320.71,84.15)
  ART10 w0.135: J10.6 239.83,142.77 257,142.77 257.99,141.78 257.99,137.92 284.47,111.44 284.47,89.09 288.88,84.68 320.18,84.68 v1(320.71,84.15)
BANK501_PS_MIO35: length 127.5
  TOP w0.173: J2.C11 v1(327.06,79.07)
  ART10 w0.135: v1(327.06,79.07) 326.58,78.59 285.89,78.59 278.27,86.21 278.27,109.58 258.47,129.38 257.1,129.38 250.03,136.45 245.24,136.45 J10.7
BANK501_PS_MIO38: length 119.5
  TOP w0.173: J2.G9 v1(320.71,81.61)
  ART10 w0.135: J10.8 243.39,142.33 247.18,142.33 247.4,142.11 247.4,140.11 247.78,139.73 252.98,139.73 282.11,110.6 282.11,87.59 287.1,82.6 319.1,82.6 320.09,81.61 v1(320.71,81.61)
BANK501_PS_MIO39: length 120.2
  TOP w0.173: J2.E10 v1(323.25,80.34)
  ART10 w0.135: v1(323.25,80.34) 322.64,79.73 286.93,79.73 279.65,87 279.65,110.01 251.77,137.9 245.8,137.9 244.37,139.32 J10.9
BANK501_PS_MIO40: length 123.3
  TOP w0.173: J2.B11 v1(328.33,79.07)
  ART10 w0.135: v1(328.33,79.07) 327.86,79.54 327.86,80.42 327.41,80.87 319.2,80.87 318.49,81.58 286.88,81.58 280.93,87.53 280.93,110.54 252.45,139.01 247.5,139.01 246.37,140.14 J10.10
BANK501_PS_MIO41: length 115.4
  TOP w0.173: J2.F9 v1(321.98,81.61)
  ART10 w0.135: J10.11 249.22,142.16 254.86,142.16 255.52,141.5 255.52,138.95 283.06,111.42 283.06,88.41 287.89,83.58 320.81,83.58 321.36,83.03 321.36,82.23 v1(321.98,81.61)
BANK505_MGT_CLK0_N: length 38.4
  TOP w0.114: U13.9 339.05,32.86 338.85,32.66 337.69,32.66 337.42,32.94 337.42,33.36 337.54,33.48 v1(337.75,33.48)
  TOP w0.173: J2.G33 v1(321.98,51.13)
  BOTTOM w0.114: v1(321.98,51.13) 321.98,50.74 322.1,50.63 326.15,50.63 326.48,50.3 326.48,49.56 326.68,49.35 336.07,49.35 339.35,46.07 339.35,39.6 337.42,37.68 337.42,33.59 337.54,33.48 v1(337.75,33.48)
BANK505_MGT_CLK0_P: length 38.4
  TOP w0.114: v1(336.83,33.48) 337.04,33.48 337.16,33.36 337.16,32.82 337.58,32.4 338.85,32.4 339.05,32.21 U13.10
  TOP w0.173: J2.F33 v1(321.98,49.86)
  BOTTOM w0.114: v1(336.83,33.48) 337.04,33.48 337.16,33.59 337.16,37.79 339.08,39.72 339.08,45.96 335.96,49.09 326.57,49.09 326.21,49.44 326.21,50.19 326.04,50.36 322.1,50.36 321.98,50.25 v1(321.98,49.86)
BANK505_MGT_CLK2_N: length 23.4
  TOP w0.114: v1(336.85,40.54) 337.06,40.54 337.18,40.42 337.18,39.79 337.73,39.23 339.18,39.23 339.6,38.82 Y7.5
  TOP w0.173: J2.E36 v1(324.52,46.05)
  BOTTOM w0.114: v1(324.52,46.05) 325.02,46.55 335.44,46.55 337.18,44.82 337.18,40.65 337.06,40.54 v1(336.85,40.54)
BANK505_MGT_CLK2_P: length 23.4
  TOP w0.114: Y7.4 339.6,39.92 339.18,39.5 337.84,39.5 337.45,39.9 337.45,40.42 337.56,40.54 v1(337.77,40.54)
  TOP w0.173: J2.D36 v1(324.52,47.32)
  BOTTOM w0.114: v1(337.77,40.54) 337.56,40.54 337.45,40.65 337.45,44.93 335.55,46.82 325.02,46.82 v1(324.52,47.32)
BANK505_MGT_RX0_N: length 55.6
  TOP w0.114: C72.2 340.07,-1.7 arc(340.24,-1.81) 340.44,-1.85 340.48,-1.85 arc(340.69,-1.81) 340.86,-1.7 341.04,-1.52
  TOP w0.173: J2.E48 324.52,30.81
  ART03 w0.102: 324.52,30.81 324.52,31.1 arc(324.59,31.26) 324.75,31.33 324.86,31.33 arc(324.99,31.35) 325.1,31.43 325.18,31.52 arc(325.31,31.7) 325.35,31.92 325.35,33.54 arc(325.37,33.66) 325.44,33.75 325.46,33.77 arc(325.55,33.83) 325.67,33.86 330.98,33.86 arc(331.48,33.76) 331.89,33.48 334.68,30.7 arc(334.96,30.28) 335.06,29.78 335.06,29.32 arc(335.03,29.21) 334.97,29.11 334.94,29.08 arc(334.89,29) 334.87,28.91 334.87,28.89 arc(334.89,28.8) 334.94,28.72 334.98,28.68 arc(335.04,28.6) 335.06,28.5 335.06,28.48 arc(335.04,28.39) 334.98,28.31 334.94,28.27 arc(334.89,28.19) 334.87,28.1 334.87,28.08 arc(334.89,27.98) 334.94,27.91 334.98,27.86 arc(335.04,27.78) 335.06,27.69 335.06,27.67 arc(335.04,27.58) 334.98,27.5 334.94,27.46 arc(334.89,27.38) 334.87,27.29 334.87,27.26 arc(334.89,27.17) 334.94,27.09 334.98,27.05 arc(335.04,26.97) 335.06,26.88 335.06,26.86 arc(335.04,26.77) 334.98,26.69 334.94,26.64 arc(334.89,26.57) 334.87,26.47 334.87,26.45 arc(334.89,26.36) 334.94,26.28 334.98,26.24 arc(335.04,26.16) 335.06,26.07 335.06,26.05 arc(335.04,25.95) 334.98,25.87 334.94,25.83 arc(334.89,25.75) 334.87,25.66 334.87,25.64 arc(334.89,25.55) 334.94,25.47 334.98,25.43 arc(335.04,25.35) 335.06,25.25 335.06,25.23 arc(335.04,25.14) 334.98,25.06 334.94,25.02 arc(334.89,24.94) 334.87,24.85 334.87,24.83 arc(334.89,24.73) 334.94,24.65 334.98,24.61 arc(335.04,24.53) 335.06,24.44 335.06,24.42 arc(335.04,24.33) 334.98,24.25 334.94,24.21 arc(334.89,24.13) 334.87,24.03 334.87,24.01 arc(334.89,23.92) 334.94,23.84 334.97,23.81 arc(335.03,23.72) 335.06,23.61 335.06,19.17 arc(335.15,18.68) 335.44,18.25 343.76,9.93 arc(344,9.57) 344.09,9.14 344.09,-0.26 arc(344.05,-0.43) 343.96,-0.57 342.9,-1.63 arc(342.64,-1.8) 342.34,-1.86 341.51,-1.86 arc(341.39,-1.84) 341.29,-1.77 341.04,-1.52
BANK505_MGT_RX0_P: length 55.6
  TOP w0.114: 341.04,-2.44 340.87,-2.27 arc(340.71,-2.16) 340.51,-2.12 340.48,-2.12 arc(340.27,-2.16) 340.1,-2.28 C73.2
  TOP w0.173: J2.D48 324.52,32.08
  ART03 w0.102: 341.04,-2.44 341.29,-2.19 arc(341.39,-2.12) 341.51,-2.1 342.34,-2.1 arc(342.73,-2.02) 343.06,-1.8 344.13,-0.73 arc(344.27,-0.52) 344.32,-0.26 344.32,9.14 arc(344.22,9.66) 343.92,10.1 335.6,18.42 arc(335.37,18.77) 335.29,19.17 335.29,29.78 arc(335.18,30.37) 334.85,30.86 332.06,33.65 arc(331.57,33.98) 330.98,34.09 325.67,34.09 arc(325.46,34.05) 325.29,33.94 325.27,33.92 arc(325.16,33.75) 325.12,33.54 325.12,31.92 arc(325.09,31.79) 325.02,31.68 324.93,31.6 arc(324.9,31.57) 324.86,31.57 324.7,31.57 arc(324.57,31.62) 324.52,31.74 324.52,32.08
BANK505_MGT_RX1_N: length 55
  TOP w0.114: C68.2 340.07,2.15 arc(340.24,2.03) 340.44,1.99 340.48,1.99 arc(340.69,2.04) 340.86,2.15 341.04,2.33
  TOP w0.173: J2.C47 327.06,32.08
  ART03 w0.102: 341.04,2.33 341.04,2.15 arc(341.09,2.03) 341.2,1.99 342.25,1.99 arc(342.29,2) 342.33,2.02 342.67,2.36 arc(342.69,2.39) 342.7,2.43 342.7,6.81 arc(342.65,7.06) 342.5,7.28 341.36,8.42 arc(341.07,8.54) 340.78,8.42 340.37,8.01 arc(339.46,8.01) 339.46,8.91 339.88,9.33 arc(339.99,9.62) 339.88,9.91 339.87,9.91 arc(339.59,10.03) 339.3,9.91 338.88,9.49 arc(337.97,9.49) 337.97,10.4 338.39,10.82 arc(338.51,11.1) 338.39,11.39 arc(338.1,11.51) 337.81,11.39 337.4,10.98 arc(336.49,10.97) 336.49,11.88 336.91,12.3 arc(337.02,12.59) 336.91,12.87 arc(336.62,12.99) 336.33,12.88 335.91,12.46 arc(335.01,12.46) 335.01,13.37 335.42,13.78 arc(335.54,14.07) 335.42,14.36 335.42,14.36 arc(335.13,14.48) 334.85,14.36 334.42,13.93 arc(333.51,13.93) 333.51,14.84 333.94,15.27 arc(334.06,15.56) 333.94,15.84 332.73,17.05 arc(332.65,17.16) 332.63,17.29 332.63,23.49 arc(332.6,23.62) 332.53,23.72 332.49,23.76 arc(332.44,23.83) 332.43,23.92 332.43,23.94 arc(332.44,24.03) 332.49,24.1 332.56,24.17 arc(332.61,24.24) 332.63,24.33 332.63,24.35 arc(332.61,24.43) 332.56,24.5 332.49,24.57 arc(332.44,24.65) 332.43,24.73 332.43,24.75 arc(332.44,24.84) 332.49,24.91 332.56,24.98 arc(332.61,25.05) 332.63,25.14 332.63,25.16 arc(332.61,25.24) 332.56,25.32 332.49,25.39 arc(332.44,25.46) 332.43,25.54 332.43,25.57 arc(332.44,25.65) 332.49,25.72 332.56,25.79 arc(332.61,25.87) 332.63,25.95 332.63,25.97 arc(332.61,26.06) 332.56,26.13 332.49,26.2 arc(332.44,26.27) 332.43,26.36 332.43,26.38 arc(332.44,26.46) 332.49,26.54 332.56,26.61 arc(332.61,26.68) 332.63,26.76 332.63,26.78 arc(332.61,26.87) 332.56,26.94 332.49,27.01 arc(332.44,27.08) 332.43,27.17 332.43,27.19 arc(332.44,27.28) 332.49,27.35 332.56,27.42 arc(332.61,27.49) 332.63,27.58 332.63,27.6 arc(332.61,27.68) 332.56,27.76 332.49,27.82 arc(332.44,27.9) 332.43,27.98 332.43,28 arc(332.44,28.09) 332.49,28.16 332.53,28.2 arc(332.6,28.31) 332.63,28.43 332.63,28.76 arc(332.53,29.25) 332.25,29.67 329.69,32.22 arc(329.28,32.5) 328.78,32.6 327.94,32.6 arc(327.61,32.53) 327.33,32.35 327.06,32.08
BANK505_MGT_RX1_P: length 55
  TOP w0.114: 341.04,1.41 340.87,1.58 arc(340.71,1.69) 340.51,1.73 340.48,1.73 arc(340.27,1.69) 340.1,1.57 C69.2
  TOP w0.173: J2.B47 327.06,33.35
  ART03 w0.102: 341.04,1.41 341.04,1.59 arc(341.09,1.7) 341.2,1.75 342.25,1.75 arc(342.38,1.78) 342.49,1.85 342.83,2.19 arc(342.91,2.3) 342.93,2.43 342.93,6.81 arc(342.86,7.15) 342.67,7.44 341.53,8.59 arc(341.07,8.78) 340.62,8.59 340.2,8.17 arc(339.63,8.17) 339.63,8.75 340.04,9.16 arc(340.23,9.62) 340.04,10.07 340.04,10.07 arc(339.59,10.26) 339.13,10.07 338.72,9.66 arc(338.14,9.66) 338.14,10.23 338.56,10.65 arc(338.75,11.1) 338.56,11.56 338.56,11.56 arc(338.1,11.75) 337.65,11.56 337.23,11.14 arc(336.66,11.14) 336.66,11.72 337.07,12.13 arc(337.26,12.59) 337.07,13.04 337.07,13.04 arc(336.62,13.23) 336.16,13.04 335.75,12.63 arc(335.17,12.63) 335.17,13.2 335.59,13.62 arc(335.78,14.07) 335.59,14.53 arc(335.13,14.71) 334.68,14.53 334.25,14.1 arc(333.68,14.1) 333.68,14.67 334.1,15.1 arc(334.29,15.56) 334.1,16.01 332.89,17.22 arc(332.87,17.25) 332.86,17.29 332.86,28.76 arc(332.75,29.34) 332.42,29.83 329.86,32.39 arc(329.37,32.72) 328.78,32.84 327.94,32.84 arc(327.61,32.9) 327.33,33.09 327.06,33.35
BANK505_MGT_RX2_N: length 73.6
  TOP w0.152: C92.2 383.04,52.21 382.44,52.21 v1(382.13,52.51)
  TOP w0.173: J2.G45 v1(321.98,35.89)
  ART03 w0.127: v1(382.13,52.51) 381.8,52.18 380.74,52.18 379.2,50.65 376.85,50.65 362.32,36.12 347.01,36.12 343.55,32.66 335.89,32.66 331.82,36.74 326.65,36.74 326.21,36.3 326.21,35.64 325.96,35.38 322.49,35.38 v1(321.98,35.89)
BANK505_MGT_RX2_P: length 73.6
  TOP w0.152: C95.2 383.04,51.9 382.44,51.9 v1(382.13,51.6)
  TOP w0.173: J2.F45 v1(321.98,34.62)
  ART03 w0.127: v1(382.13,51.6) 381.8,51.93 380.84,51.93 379.31,50.4 376.96,50.4 362.43,35.86 347.12,35.86 343.65,32.4 335.79,32.4 331.71,36.48 326.76,36.48 326.47,36.19 326.47,35.53 326.06,35.13 322.49,35.13 v1(321.98,34.62)
BANK505_MGT_TX0_N: length 58.3
  TOP w0.114: C74.2 336.51,-3.63 arc(336.68,-3.74) 336.88,-3.78 336.93,-3.78 arc(337.13,-3.74) 337.31,-3.62 v1(337.48,-3.45)
  TOP w0.173: J2.C45 v1(327.06,34.62)
  ART10 w0.102: v1(327.06,34.62) 327.33,34.89 arc(327.61,35.07) 327.94,35.14 333.17,35.14 arc(333.46,35.08) 333.71,34.92 334.59,34.03 arc(334.76,33.79) 334.82,33.49 334.82,23.99 arc(334.93,23.41) 335.26,22.91 343.75,14.42 arc(343.77,14.39) 343.78,14.35 343.78,2.8 arc(343.76,2.68) 343.69,2.58 343.65,2.54 arc(343.6,2.47) 343.59,2.38 343.59,2.36 arc(343.6,2.27) 343.65,2.2 343.71,2.14 arc(343.76,2.06) 343.78,1.97 343.78,1.95 arc(343.76,1.86) 343.71,1.79 343.65,1.73 arc(343.6,1.65) 343.59,1.57 343.59,1.55 arc(343.6,1.46) 343.65,1.38 343.71,1.32 arc(343.76,1.25) 343.78,1.16 343.78,1.14 arc(343.76,1.05) 343.71,0.98 343.65,0.92 arc(343.6,0.84) 343.59,0.75 343.59,0.73 arc(343.6,0.64) 343.65,0.57 343.71,0.51 arc(343.76,0.43) 343.78,0.35 343.78,0.33 arc(343.76,0.24) 343.71,0.16 343.65,0.1 arc(343.6,0.03) 343.59,-0.06 343.59,-0.08 arc(343.6,-0.17) 343.65,-0.24 343.71,-0.3 arc(343.76,-0.38) 343.78,-0.47 343.78,-0.49 arc(343.76,-0.57) 343.71,-0.65 343.65,-0.71 arc(343.6,-0.78) 343.59,-0.87 343.59,-0.89 arc(343.6,-0.98) 343.65,-1.06 343.71,-1.12 arc(343.76,-1.19) 343.78,-1.28 343.78,-1.3 arc(343.76,-1.39) 343.71,-1.46 343.65,-1.52 arc(343.6,-1.6) 343.59,-1.69 343.59,-1.71 arc(343.6,-1.79) 343.65,-1.87 343.69,-1.91 arc(343.76,-2.01) 343.78,-2.12 343.78,-2.3 arc(343.72,-2.62) 343.54,-2.89 342.92,-3.51 arc(342.62,-3.71) 342.25,-3.78 338.05,-3.78 arc(337.84,-3.74) 337.66,-3.62 v1(337.48,-3.45)
BANK505_MGT_TX0_P: length 58.3
  TOP w0.114: C75.2 336.54,-4.2 arc(336.72,-4.09) 336.92,-4.04 336.96,-4.04 arc(337.15,-4.08) 337.32,-4.19 v1(337.48,-4.36)
  TOP w0.173: J2.B45 v1(327.06,35.89)
  ART10 w0.102: v1(327.06,35.89) 327.33,35.63 arc(327.61,35.44) 327.94,35.38 333.17,35.38 arc(333.55,35.3) 333.88,35.08 334.76,34.2 arc(334.98,33.88) 335.05,33.49 335.05,23.99 arc(335.15,23.5) 335.43,23.08 343.92,14.59 arc(343.99,14.48) 344.02,14.35 344.02,-2.3 arc(343.94,-2.71) 343.7,-3.06 343.09,-3.67 arc(342.71,-3.93) 342.25,-4.02 338.05,-4.02 arc(337.84,-4.06) 337.66,-4.18 v1(337.48,-4.36)
BANK505_MGT_TX1_N: length 57.8
  TOP w0.114: C70.2 336.51,0.22 arc(336.68,0.11) 336.88,0.07 336.93,0.07 arc(337.13,0.11) 337.31,0.23 v1(337.48,0.4)
  TOP w0.173: J2.E44 v1(324.52,35.89)
  ART10 w0.102: v1(324.52,35.89) 324.52,36.31 arc(324.55,36.38) 324.62,36.41 324.77,36.41 arc(325.01,36.31) 325.12,36.06 325.12,32.18 arc(325.39,31.52) 326.05,31.25 331.43,31.25 arc(332.34,30.87) 332.71,29.96 332.71,22.75 arc(332.83,22.17) 333.16,21.68 333.86,20.98 arc(333.97,20.69) 333.86,20.41 333.45,20 arc(333.45,19.09) 334.36,19.09 334.76,19.5 arc(335.05,19.62) 335.34,19.5 arc(335.46,19.21) 335.34,18.92 334.93,18.51 arc(334.93,17.6) 335.84,17.6 336.25,18.01 arc(336.54,18.13) 336.82,18.01 336.82,18.01 arc(336.94,17.72) 336.82,17.44 336.42,17.03 arc(336.42,16.12) 337.33,16.12 337.83,16.62 arc(338.02,16.7) 338.21,16.62 338.57,16.26 arc(338.85,15.85) 338.95,15.35 338.95,6.41 arc(338.93,6.29) 338.86,6.19 338.82,6.15 arc(338.77,6.07) 338.75,5.99 338.75,5.97 arc(338.77,5.88) 338.82,5.81 338.88,5.74 arc(338.93,5.67) 338.95,5.58 338.95,5.56 arc(338.93,5.48) 338.88,5.4 338.82,5.33 arc(338.77,5.26) 338.75,5.18 338.75,5.16 arc(338.77,5.07) 338.82,5 338.88,4.93 arc(338.93,4.86) 338.95,4.77 338.95,4.75 arc(338.93,4.66) 338.88,4.59 338.82,4.52 arc(338.77,4.45) 338.75,4.36 338.75,4.34 arc(338.77,4.26) 338.82,4.18 338.88,4.12 arc(338.93,4.04) 338.95,3.96 338.95,3.94 arc(338.93,3.85) 338.88,3.78 338.82,3.71 arc(338.77,3.64) 338.75,3.55 338.75,3.53 arc(338.77,3.44) 338.82,3.37 338.88,3.3 arc(338.93,3.23) 338.95,3.14 338.95,3.12 arc(338.93,3.04) 338.88,2.96 338.82,2.9 arc(338.77,2.82) 338.75,2.74 338.75,2.72 arc(338.77,2.63) 338.82,2.56 338.88,2.49 arc(338.93,2.42) 338.95,2.33 338.95,2.31 arc(338.93,2.22) 338.88,2.15 338.82,2.08 arc(338.77,2.01) 338.75,1.92 338.75,1.9 arc(338.77,1.82) 338.82,1.74 338.86,1.7 arc(338.93,1.6) 338.95,1.48 338.95,0.61 arc(338.79,0.23) 338.4,0.06 338.05,0.06 arc(337.84,0.11) 337.66,0.23 v1(337.48,0.4)
BANK505_MGT_TX1_P: length 57.8
  TOP w0.114: C71.2 336.54,-0.35 arc(336.72,-0.24) 336.92,-0.2 336.96,-0.2 arc(337.15,-0.24) 337.32,-0.35 v1(337.48,-0.51)
  TOP w0.173: J2.D44 v1(324.52,37.16)
  ART10 w0.102: v1(337.48,-0.51) 337.66,-0.34 arc(337.84,-0.21) 338.05,-0.17 338.4,-0.17 arc(338.96,0.06) 339.19,0.61 339.19,15.35 arc(339.07,15.94) 338.74,16.43 338.38,16.79 arc(338.02,16.94) 337.66,16.79 337.16,16.29 arc(336.58,16.29) 336.58,16.86 336.99,17.27 arc(337.18,17.72) 336.99,18.18 336.99,18.18 arc(336.54,18.37) 336.08,18.18 335.67,17.77 arc(335.1,17.77) 335.1,18.35 335.51,18.75 arc(335.69,19.21) 335.51,19.66 335.51,19.66 arc(335.05,19.85) 334.6,19.66 334.19,19.26 arc(333.61,19.26) 333.61,19.83 334.02,20.24 arc(334.21,20.69) 334.02,21.15 333.33,21.84 arc(333.05,22.26) 332.95,22.75 332.95,29.96 arc(332.5,31.04) 331.43,31.49 326.05,31.49 arc(325.56,31.69) 325.35,32.18 325.35,36.06 arc(325.18,36.47) 324.77,36.65 324.62,36.65 arc(324.55,36.68) 324.52,36.75 v1(324.52,37.16)
BANK505_MGT_TX2_N: length 76.7
  TOP w0.152: C97.2 383.04,50.2 382.44,50.2 v1(382.13,50.51)
  TOP w0.173: J2.G43 v1(321.98,37.16)
  ART03 w0.127: v1(382.13,50.51) 382.46,50.18 382.84,50.18 383.34,50.67 383.34,53.17 382.88,53.62 380.96,53.62 379.33,51.99 376.97,51.99 376.82,51.84 376.82,51.54 376.67,51.39 376.46,51.39 376.31,51.54 376.31,51.84 376.16,51.99 375.79,51.99 362.1,38.3 345.87,38.3 343.94,36.37 337.66,36.37 336.36,37.67 322.49,37.67 v1(321.98,37.16)
BANK505_MGT_TX2_P: length 76.7
  TOP w0.152: C96.2 383.04,49.9 382.44,49.9 v1(382.13,49.59)
  TOP w0.173: J2.F43 v1(321.98,38.43)
  ART03 w0.127: v1(382.13,49.59) 382.13,49.62 382.43,49.92 382.95,49.92 383.59,50.57 383.59,53.27 382.99,53.88 380.86,53.88 379.22,52.24 375.68,52.24 362,38.56 345.76,38.56 343.83,36.63 337.77,36.63 336.47,37.92 322.49,37.92 v1(321.98,38.43)
CLK_100M_N: length 16.2
  TOP w0.114: U13.7 344.75,32.21 344.55,32.01 343.82,32.01 343.5,32.33 343.5,33.56 343.84,33.9 345.11,33.9 345.32,33.69 345.57,33.69 345.78,33.9 346.03,33.9 346.23,33.69 346.48,33.69 346.69,33.9 346.94,33.9 347.15,33.69 347.4,33.69 347.61,33.9 347.85,33.9 348.06,33.69 348.31,33.69 348.52,33.9 348.77,33.9 348.98,33.69 349.23,33.69 349.43,33.9 349.68,33.9 349.89,33.69 350.14,33.69 350.35,33.9 350.6,33.9 350.81,33.69 351.05,33.69 351.26,33.9 351.82,33.9 352.41,33.31 352.41,32.56 352,32.15 XS2.5
CLK_100M_P: length 16.3
  TOP w0.114: XS2.4 353.1,32.15 352.68,32.56 352.68,33.42 351.93,34.17 343.73,34.17 343.23,33.67 343.23,32.22 343.71,31.75 344.55,31.75 344.75,31.56 U13.6
CLKIN0_N: length 159.6
  TOP w0.173: J2.G4 v1(320.71,87.96)
  ART03 w0.102: v1(320.71,87.96) 321.13,87.96 arc(321.2,87.93) 321.23,87.86 321.23,87.46 321.12,87.34 310.68,87.34 308.61,89.41 288.41,89.41 258.83,59.84 258.83,-19.78 arc(258.81,-19.9) 258.75,-20 v1(258.5,-20.25)
  BOTTOM w0.114: v1(258.5,-20.25) 258.82,-20.57 258.82,-21.08 258.46,-21.45 CAB75.2
CLKIN0_P: length 159.6
  TOP w0.173: J2.F4 v1(321.98,87.96)
  ART03 w0.102: v1(321.98,87.96) 321.57,87.96 arc(321.5,87.93) 321.47,87.86 321.47,87.36 321.21,87.11 310.58,87.11 308.51,89.18 288.5,89.18 259.07,59.74 259.07,-19.78 arc(259.09,-19.9) 259.16,-20 v1(259.41,-20.25)
  BOTTOM w0.114: v1(259.41,-20.25) 259.09,-20.57 259.09,-21.08 259.45,-21.45 CAB74.2
DU+: length 29
  TOP w0.114: J4.B6 401.86,8.37 401.98,8.25 402.54,8.25 v1(402.76,8.47) ; v1(392.19,2.97) 391.97,3.19 391.97,3.45 391.61,3.81 390.37,3.81 390.06,3.5 389.51,3.5 389.39,3.61 U2.8 ; J4.A6 399.26,7.62 398.89,7.99 398.38,7.99 v1(398.16,7.76) 397.93,7.99 397.58,7.99 D2.3
  ART10 w0.102: v1(402.76,8.47) 403,8.24 403.94,8.24 404.33,7.86 404.33,6.47 403.78,5.93 400.29,5.93 399.6,6.62 399.6,7.67 399.27,8 398.39,8 v1(398.16,7.76) 397.92,8 396.12,8 391.95,3.83 391.95,3.2 v1(392.19,2.97)
DU-: length 28.9
  TOP w0.114: v1(402.76,7.76) 402.54,7.99 401.98,7.99 401.86,7.87 J4.B7 ; J4.A7 399.26,8.62 398.9,8.25 398.38,8.25 v1(398.16,8.47) 397.93,8.25 397.63,8.25 D1.3 ; U2.7 389.39,3.11 389.51,3.23 390.17,3.23 390.48,3.54 391.5,3.54 391.7,3.34 391.7,3.19 v1(391.48,2.97)
  ART10 w0.102: v1(402.76,7.76) 403,8 403.85,8 404.09,7.76 404.09,6.57 403.68,6.16 403,6.16 402.88,6.28 402.88,6.31 402.76,6.43 402.6,6.43 402.48,6.31 402.48,6.28 402.36,6.16 402.19,6.16 402.07,6.28 402.07,6.31 401.95,6.43 401.78,6.43 401.66,6.31 401.66,6.28 401.54,6.16 401.38,6.16 401.26,6.28 401.26,6.31 401.14,6.43 400.97,6.43 400.85,6.31 400.85,6.28 400.73,6.16 400.38,6.16 399.83,6.71 399.83,7.77 399.37,8.24 398.39,8.24 v1(398.16,8.47) 397.92,8.24 396.02,8.24 391.72,3.93 391.72,3.2 v1(391.48,2.97)
EECLK: length 7.4
  TOP w0.173: U2.62 v1(387.08,-1.47) 387.08,-1.84 387.4,-2.16 387.4,-4.11 386.81,-4.7 U10.2
  BOTTOM w0.173: v1(387.08,-1.47) 386.95,-1.6 R19.1
EECS: length 9.8
  TOP w0.173: U10.1 386.98,-5.35 387.96,-4.37 v1(387.96,-2.44) 387.96,-1.88 387.58,-1.5 U2.63
  BOTTOM w0.173: R17.1 386.79,-3.61 v1(387.96,-2.44)
EEDATA: length 6.1
  TOP w0.173: U10.3 385.69,-4.05 385.9,-3.83 R18.2 386.72,-3.83 386.85,-3.69 v1(386.85,-2.53) 386.58,-2.25 U2.61
  BOTTOM w0.173: R20.1 386.78,-2.6 v1(386.85,-2.53)
FT223_UART0_RX: length 9.5
  TOP w0.173: R14.1 381,10.54 377.99,7.53 377.99,5.61 378.49,5.11 U2.38
FT223_UART0_TX: length 9.8
  TOP w0.173: R16.1 378.2,9.14 377.19,8.13 377.19,5.46 378.04,4.61 U2.39
GPS_USB_DN: length 39.6
  TOP w0.114: UG1.5 233.04,-7.25 232.62,-7.66 232.62,-8.28 v1(232.94,-8.6)
  BOTTOM w0.114: JU1.2 243.98,-27.95 243.98,-10.28 241.02,-7.33 240.66,-7.33 240.53,-7.46 240.53,-7.64 240.4,-7.77 240.21,-7.77 240.07,-7.64 240.07,-7.46 239.94,-7.33 239.75,-7.33 239.61,-7.46 239.61,-7.64 239.48,-7.77 239.29,-7.77 239.16,-7.64 239.16,-7.46 239.02,-7.33 238.83,-7.33 238.7,-7.46 238.7,-7.64 238.57,-7.77 238.38,-7.77 238.24,-7.64 238.24,-7.46 238.11,-7.33 237.92,-7.33 237.79,-7.46 237.79,-7.64 237.65,-7.77 237.46,-7.77 237.33,-7.64 237.33,-7.46 237.2,-7.33 237.01,-7.33 236.87,-7.46 236.87,-7.64 236.74,-7.77 236.55,-7.77 236.41,-7.64 236.41,-7.46 236.28,-7.33 236.09,-7.33 235.96,-7.46 235.96,-7.64 235.82,-7.77 235.63,-7.77 235.5,-7.64 235.5,-7.46 235.37,-7.33 235.18,-7.33 235.04,-7.46 235.04,-7.64 234.91,-7.77 234.72,-7.77 234.59,-7.64 234.59,-7.46 234.45,-7.33 234.26,-7.33 234.13,-7.46 234.13,-7.64 233.99,-7.77 233.81,-7.77 233.67,-7.64 233.67,-7.46 233.54,-7.33 233.19,-7.33 232.59,-7.92 232.59,-8.47 232.73,-8.6 v1(232.94,-8.6)
GPS_USB_DP: length 39.7
  TOP w0.114: v1(232.03,-8.6) 232.35,-8.28 232.35,-7.69 231.94,-7.27 UG1.6
  BOTTOM w0.114: JU1.3 243.48,-30.43 244.31,-30.43 244.7,-30.03 244.7,-29.16 244.25,-28.7 244.25,-10.17 241.13,-7.06 233.08,-7.06 232.33,-7.81 232.33,-8.49 232.21,-8.6 v1(232.03,-8.6)
INTVCC1: length 8.6
  TOP w0.381: U19.K5 v1(243.01,126.16) ; U19.J4 v1(241.74,124.89) ; U19.F4 v1(236.66,124.89) ; U19.B6 v1(231.58,127.43) ; U19.L6 v1(244.28,127.43) ; U19.E6 v1(235.39,127.43) ; U19.C4 v1(232.85,124.89) ; U19.H6 v1(240.47,127.43)
  BOTTOM w0.508: v1(241.74,124.89) 242.12,124.89 242.45,124.55 RP10.1
JTAG_R_TCK: length 6
  TOP w0.173: R6.1 392.17,10.42 389.36,7.61 U2.16
JTAG_R_TDI: length 4
  TOP w0.173: U2.17 388.08,9.2 389.38,10.5 R11.1
JTAG_R_TDO: length 3.9
  TOP w0.173: R12.1 386.58,10.93 387.58,9.93 U2.18
JTAG_R_TMS: length 6.4
  TOP w0.173: R3.1 383.79,10.29 384.05,10.03 386.72,10.03 387.08,9.67 U2.19
JTAG_TCK: length 120.2
  TOP w0.173: U4.4 392.17,15.54 v1(392.68,15.03) 393.31,15.67 R21.1 ; J2.E28 v1(324.52,57.48)
  ART05 w0.14: v1(392.68,15.03) 392.68,12.5 391.28,11.1 362.43,11.1 361.67,11.86 348.86,11.86 340.65,20.07 340.65,26.53 343.05,28.93 343.05,35.21 344.88,37.04 344.88,43.2 343.21,44.86 343.21,46.24 330.27,59.18 327.91,59.18 327.58,58.85 327.58,58.38 326.19,56.98 325.02,56.98 v1(324.52,57.48)
  BOTTOM w0.173: R10.2 392.04,17.81 392.68,17.17 v1(392.68,15.03)
